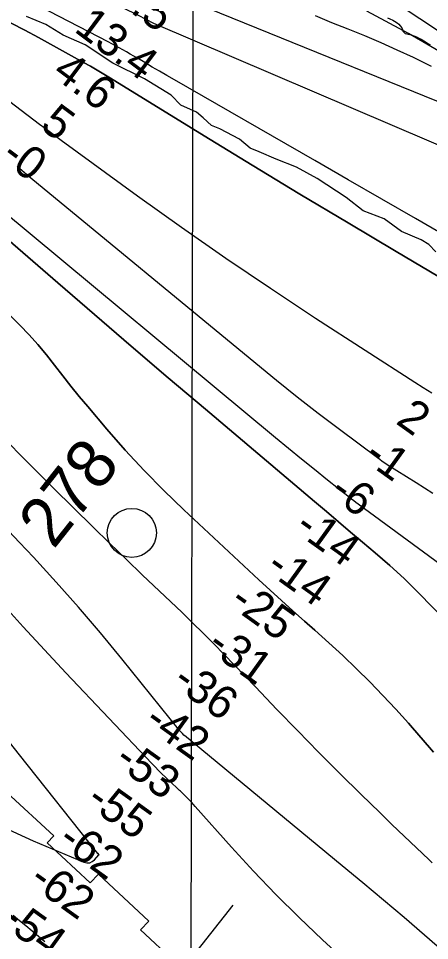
# Model space of a CAD drawing. Extents: x 3187622 to 3225504, y 800805 to 826213.
# Drawn here: x 3201935 to 3202773, y 814771 to 816652 of the extents above; entities that cross this region are included whole.
import ezdxf

# ---------------------------------------------------------------- set-up
doc = ezdxf.new("R2010")
doc.units = 0
for name, color, linetype in [('V-GRID-MAJR', 7, 'Continuous'), ('V-RIVR-EDGE', 7, 'Continuous'), ('V-RIVR-IDEN', 7, 'Continuous'), ('V-RIVR-MILE', 7, 'Continuous'), ('V-RIVR-RANG', 7, 'Continuous'), ('V-ROAD-CNTR', 7, 'Continuous'), ('V-RRAP-RVMT', 7, 'Continuous'), ('V-SITE-VEGE', 7, 'Continuous'), ('V-TOPO-DPTH', 7, 'Continuous'), ('V-TOPO-MAJR', 7, 'Continuous'), ('V-TOPO-MINR', 7, 'Continuous'), ('V-TOPO-WATR', 7, 'Continuous')]:
    doc.layers.add(name, color=color, linetype=linetype)

msp = doc.modelspace()

# ---------------------------------------------------------------- linework, layer by layer
at = {"layer": 'V-GRID-MAJR'}
msp.add_spline([(3202269.1, 806226.1), (3202282.3, 812285.3), (3202295.5, 818347.5), (3202308.8, 824409.7), (3202308.8, 824412.8)], degree=3, dxfattribs=at)
at = {"layer": 'V-RIVR-EDGE'}
msp.add_lwpolyline([(3202785.2, 816176.3), (3202770.9, 816190.7), (3202755.7, 816200.7), (3202715.3, 816217.4), (3202680.2, 816243.5), (3202637.6, 816259.7), (3202602.9, 816286.8), (3202543.5, 816325.6), (3202501.8, 816348.7), (3202460.1, 816364.9), (3202425.4, 816379.8), (3202407.1, 816387.2), (3202385.4, 816405.5), (3202345.5, 816426.9), (3202328.6, 816433.9), (3202311.6, 816449.6), (3202298.2, 816460.9), (3202266.1, 816475.4), (3202246.1, 816495.8), (3202191.9, 816529), (3202127.6, 816560.5), (3202071.2, 816598), (3202026.5, 816618.1), (3201990.9, 816639.5), (3201951.8, 816656.1)], dxfattribs=at)
at = {"layer": 'V-RIVR-MILE'}
msp.add_circle((3202166.4, 815602.7), 50, dxfattribs=at)
at = {"layer": 'V-RIVR-RANG'}
msp.add_line((3201900.2, 814248.2), (3202372.9, 814843.3), dxfattribs=at)
at = {"layer": 'V-ROAD-CNTR'}
msp.add_spline([(3201024.1, 823274.7), (3201018, 823194.2), (3201004.7, 822963.7), (3200987.4, 822858.7), (3200966.9, 822788.4), (3200937.8, 822670.8), (3200879.4, 822446.8), (3200861.2, 822331.3), (3200852.3, 822205.9), (3200846, 822103), (3200850.5, 822002.7), (3200859.8, 821900.4), (3200873.1, 821709.1), (3200906.2, 821470.9), (3200956.6, 821171.3), (3200981.8, 821020.5), (3201004.4, 820882.9), (3201024.9, 820767.6), (3201030.7, 820687.4), (3201025.1, 820574.8), (3201019.7, 820485.6), (3201009.9, 820413.7), (3200981.8, 820299.2), (3200938.6, 820153.1), (3200919.7, 820054.1), (3200905.9, 819899.8), (3200911.1, 819808), (3200923.6, 819715), (3200943.7, 819632.5), (3200990, 819544.5), (3201077.6, 819388.7), (3201164.6, 819241.3), (3201215.4, 819169.2), (3201320.5, 819031.2), (3201438.3, 818874.6), (3201472.9, 818830.2), (3201517.8, 818788.5), (3201613.7, 818704.1), (3201703.7, 818596), (3201763.8, 818510.5), (3201836.1, 818397.9), (3201893.8, 818288.1), (3201910, 818246.3), (3201920.9, 818198.1), (3201929.8, 818155.8), (3201937.9, 818094.1), (3201957.7, 817998.6), (3201977.9, 817926.4), (3202055.4, 817776.5), (3202147, 817624), (3202184.4, 817575.3), (3202228.3, 817509.6), (3202265.9, 817465), (3202335.4, 817389.3), (3202595.4, 817156.1), (3202698.6, 817066.2), (3202845.2, 816933.8), (3202967.2, 816832.3), (3203084.1, 816744.2), (3203205.8, 816662.3), (3203334.5, 816585.9), (3203420.1, 816528.7), (3203529.1, 816448.4), (3203624.3, 816386.4), (3203720.3, 816332.5), (3203800.7, 816304.6), (3203929.1, 816241.3), (3204015.1, 816192.4), (3204112.5, 816105.4), (3204200.5, 816023.3)], degree=3, dxfattribs=at)
at = {"layer": 'V-RRAP-RVMT'}
for p, q in [((3202007.2, 814984.9), (3201912.1, 815073.5)), ((3201994, 814970.7), (3202007.2, 814984.9)), ((3202081.8, 814888.9), (3201994, 814970.7)), ((3202098.4, 814906.7), (3202081.8, 814888.9)), ((3202200.8, 814811.2), (3202098.4, 814906.7)), ((3202184.1, 814793.3), (3202200.8, 814811.2)), ((3202271.8, 814711.4), (3202184.1, 814793.3))]:
    msp.add_line(p, q, dxfattribs=at)
at = {"layer": 'V-SITE-VEGE'}
msp.add_lwpolyline([(3202687.1, 816653.4), (3202691.7, 816650.9), (3202697.9, 816648.5), (3202701.3, 816646.6), (3202706.4, 816643), (3202709.9, 816640.3), (3202712.9, 816637.2), (3202715.8, 816632.7), (3202717.2, 816629.3), (3202718.4, 816625.7), (3202722.9, 816621.5), (3202726.1, 816620.6), (3202735, 816618.5), (3202742.3, 816616.1), (3202747.1, 816613.6), (3202751, 816612), (3202755.8, 816609.5), (3202766.6, 816602.8), (3202770.7, 816600.4), (3202773.5, 816599.1)], dxfattribs=at)
at = {"layer": 'V-TOPO-DPTH'}
for points in [[(3204217.8, 815592.6), (3203668.9, 815938.5), (3203655.2, 815947.1), (3203641.4, 815955.7), (3203627.7, 815964.2), (3203613.9, 815972.7), (3203478, 816056), (3203410.2, 816096.5), (3203341.7, 816135.7), (3203272.2, 816173.1), (3203202, 816209.3), (3203099.7, 816260.5), (3203080, 816269.9), (3203060.2, 816279), (3203040.1, 816287.4), (3203019.7, 816295.4), (3202210.8, 816641.7), (3202179.6, 816657.9), (3202148.3, 816673.9), (3202116.9, 816689.7), (3202024, 816735.9), (3201946.1, 816774.7), (3201868.2, 816813.6)], [(3201920.7, 816642), (3201948.7, 816628), (3201976.3, 816613.2), (3202068.1, 816562.1), (3202082, 816554.3), (3202095.8, 816546.3), (3202109.4, 816538.2), (3202123.1, 816529.9), (3202313.6, 816412.6), (3202411.1, 816353), (3202508.7, 816293.7), (3202606.7, 816234.9), (3202704.9, 816176.4), (3202877.5, 816074.1)], [(3201920.7, 816642), (3201948.7, 816628), (3201976.3, 816613.2), (3202068.1, 816562.1), (3202082, 816554.3), (3202095.8, 816546.3), (3202109.4, 816538.2), (3202123.1, 816529.9), (3202313.6, 816412.6), (3202411.1, 816353), (3202508.7, 816293.7), (3202606.7, 816234.9), (3202704.9, 816176.4), (3202877.5, 816074.1)], [(3202779.4, 815683.2), (3202745, 815704.9), (3202686.6, 815741.9), (3202681.5, 815745.2), (3202676.4, 815748.7), (3202671.4, 815752.2), (3202666.5, 815755.8), (3202589.3, 815813.6), (3202546, 815846.5), (3202503.1, 815879.8), (3202460.6, 815913.7), (3202418.5, 815948.1), (3201960.9, 816326.1), (3201951.5, 816333.9), (3201942.3, 816341.9), (3201933.1, 816350)], [(3202779.4, 815683.2), (3202745, 815704.9), (3202686.6, 815741.9), (3202681.5, 815745.2), (3202676.4, 815748.7), (3202671.4, 815752.2), (3202666.5, 815755.8), (3202589.3, 815813.6), (3202546, 815846.5), (3202503.1, 815879.8), (3202460.6, 815913.7), (3202418.5, 815948.1), (3201960.9, 816326.1), (3201951.5, 816333.9), (3201942.3, 816341.9), (3201933.1, 816350)], [(3201903.4, 816209.7), (3202015.4, 816112.7), (3202090.3, 816048), (3202165.3, 815983.5), (3202240.6, 815919.3), (3202316, 815855.2), (3202538.2, 815666.8), (3202562.7, 815646.1), (3202587.2, 815625.3), (3202611.8, 815604.6), (3202636.3, 815583.9), (3202661.8, 815562.3), (3202691.7, 815536.4), (3202721, 815509.9), (3203068.5, 815159.2), (3203089.5, 815141.7), (3203110.6, 815124.5), (3203131.9, 815107.6), (3203153.4, 815090.8), (3203574.3, 814699.2)], [(3203574.3, 814699.2), (3203153.4, 815090.8), (3203131.9, 815107.6), (3203110.6, 815124.5), (3203089.5, 815141.7), (3203068.5, 815159.2), (3202721, 815509.9), (3202691.7, 815536.4), (3202661.8, 815562.3), (3202636.3, 815583.9), (3202611.8, 815604.6), (3202587.2, 815625.3), (3202562.7, 815646.1), (3202538.2, 815666.8), (3202316, 815855.2), (3202240.6, 815919.3), (3202165.3, 815983.5), (3202090.3, 816048), (3202015.4, 816112.7), (3201903.4, 816209.7)], [(3201836.2, 816126.5), (3201938.1, 816026.2), (3201957, 816006.8), (3201975.2, 815986.9), (3201992.5, 815966.2), (3202009.1, 815945), (3202025.6, 815923.4), (3202042.2, 815902.1), (3202059.2, 815881.1), (3202076.5, 815860.3), (3202115.2, 815814.5), (3202152.7, 815771.6), (3202191.3, 815729.7), (3202231.3, 815689.1), (3202272.3, 815649.5), (3202425, 815507.2), (3202448.1, 815485.9), (3202471.2, 815464.8), (3202494.5, 815443.8), (3202518, 815423), (3202539.1, 815404.3), (3202567.7, 815378.6), (3202595.9, 815352.5), (3202623.5, 815325.8), (3202650.8, 815298.8), (3202677.5, 815271.2), (3202703.8, 815243.2), (3202729.5, 815214.6), (3202754.7, 815185.6), (3202755.3, 815184.9), (3202780.6, 815155.4)], [(3202780.6, 815155.4), (3202755.3, 815184.9), (3202754.7, 815185.6), (3202729.5, 815214.6), (3202703.8, 815243.2), (3202677.5, 815271.2), (3202650.8, 815298.8), (3202623.5, 815325.8), (3202595.9, 815352.5), (3202567.7, 815378.6), (3202539.1, 815404.3), (3202518, 815423), (3202494.5, 815443.8), (3202471.2, 815464.8), (3202448.1, 815485.9), (3202425, 815507.2), (3202272.3, 815649.5), (3202231.3, 815689.1), (3202191.3, 815729.7), (3202152.7, 815771.6), (3202115.2, 815814.5), (3202076.5, 815860.3), (3202059.2, 815881.1), (3202042.2, 815902.1), (3202025.6, 815923.4), (3202009.1, 815945), (3201992.5, 815966.2), (3201975.2, 815986.9), (3201957, 816006.8), (3201938.1, 816026.2), (3201836.2, 816126.5)], [(3201902.1, 815799.5), (3201954.4, 815746.6), (3202007.1, 815694.1), (3202087.5, 815614.8), (3202121, 815582), (3202154.6, 815549.3), (3202188.3, 815516.8), (3202222.3, 815484.4), (3202246, 815461.9), (3202268, 815440.8), (3202289.9, 815419.5), (3202311.6, 815398.1), (3202333.1, 815376.5), (3202354.4, 815354.7), (3202375.7, 815332.9), (3202396.9, 815310.9), (3202418, 815288.9), (3202461.8, 815242.9), (3202504.1, 815199), (3202546.7, 815155.4), (3202589.8, 815112.2), (3202633.2, 815069.3), (3202671.1, 815032.3), (3202695.8, 815008.3), (3202720.7, 814984.3), (3202745.7, 814960.5), (3202770.9, 814936.8), (3202777.9, 814930.2)], [(3202777.9, 814930.2), (3202770.9, 814936.8), (3202745.7, 814960.5), (3202720.7, 814984.3), (3202695.8, 815008.3), (3202671.1, 815032.3), (3202633.2, 815069.3), (3202589.8, 815112.2), (3202546.7, 815155.4), (3202504.1, 815199), (3202461.8, 815242.9), (3202418, 815288.9), (3202396.9, 815310.9), (3202375.7, 815332.9), (3202354.4, 815354.7), (3202333.1, 815376.5), (3202311.6, 815398.1), (3202289.9, 815419.5), (3202268, 815440.8), (3202246, 815461.9), (3202222.3, 815484.4), (3202188.3, 815516.8), (3202154.6, 815549.3), (3202121, 815582), (3202087.5, 815614.8), (3202007.1, 815694.1), (3201954.4, 815746.6), (3201902.1, 815799.5)]]:
    msp.add_lwpolyline(points, dxfattribs=at)
at = {"layer": 'V-TOPO-MAJR'}
for points in [[(3204255.2, 815652.9), (3203706.2, 815992.5), (3203701.3, 815995.5), (3203696.3, 815998.6), (3203691.4, 816001.7), (3203686.5, 816004.8), (3203678.5, 816009.9), (3203677.7, 816010.4), (3203675.9, 816011.6), (3203675, 816012.1), (3203666.3, 816017.8), (3203661.1, 816021.2), (3203655.8, 816024.6), (3203650.6, 816028), (3203645.4, 816031.5), (3203179.2, 816341.1), (3203154, 816357.7), (3203128.8, 816374.2), (3203103.5, 816390.5), (3203078, 816406.8), (3202894.2, 816523.3), (3202812.3, 816573.3), (3202729.4, 816621.4), (3202645, 816666.8)], [(3202803.7, 814746.6), (3202762.1, 814782.5), (3202720.6, 814818.1), (3202678.9, 814853.6), (3202637, 814888.8), (3202594.9, 814923.8), (3202273.5, 815189.5), (3202273.1, 815189.9), (3202272.2, 815190.6), (3202269.2, 815193.5), (3202266, 815197), (3202264.8, 815198.5), (3202264.2, 815199.2), (3202146.1, 815346.1), (3202102.5, 815399.1), (3202058, 815451.4), (3202012.4, 815502.6), (3201966, 815553.1), (3201937.8, 815583.1), (3201904.7, 815618)]]:
    msp.add_lwpolyline(points, dxfattribs=at)
at = {"layer": 'V-TOPO-MINR'}
for points in [[(3204027.1, 815824.8), (3203733.7, 816024.2), (3203716.7, 816035.6), (3203699.6, 816046.7), (3203682.3, 816057.6), (3203665, 816068.4), (3203441.7, 816204), (3203391.4, 816234.9), (3203341.2, 816266), (3203291.3, 816297.4), (3203241.6, 816329.1), (3203156.6, 816383.7), (3203149.4, 816388.3), (3203142.3, 816393), (3203135.2, 816397.6), (3203128.1, 816402.3), (3202564.1, 816776.6), (3202531, 816798.2), (3202497.7, 816819.6), (3202464.1, 816840.5), (3202430.4, 816861.1), (3202427.8, 816862.7), (3201556.2, 817191.3)], [(3204217.8, 815592.6), (3203668.9, 815938.5), (3203655.2, 815947.1), (3203641.4, 815955.7), (3203627.7, 815964.2), (3203613.9, 815972.7), (3203478, 816056), (3203410.2, 816096.5), (3203341.7, 816135.7), (3203272.2, 816173.1), (3203202, 816209.3), (3203099.7, 816260.5), (3203080, 816269.9), (3203060.2, 816279), (3203040.1, 816287.4), (3203019.7, 816295.4), (3202210.8, 816641.7), (3202179.6, 816657.9), (3202148.3, 816673.9), (3202116.9, 816689.7), (3202024, 816735.9), (3201946.1, 816774.7), (3201868.2, 816813.6)], [(3202812.1, 816204.4), (3202743.8, 816244), (3202675.5, 816283.5), (3202607.1, 816323), (3202538.7, 816362.4), (3202253, 816526.7), (3202237.9, 816535.4), (3202222.9, 816544.1), (3202207.9, 816552.9), (3202192.9, 816561.8), (3202177.6, 816570.8), (3202170.2, 816575.1), (3202162.9, 816579.4), (3202155.5, 816583.7), (3202148.1, 816587.9), (3202140.6, 816592.1), (3202133.2, 816596.2), (3202125.6, 816600.2), (3202118.1, 816604.2), (3201878.6, 816728.5)], [(3202959.8, 816413.4), (3202273.9, 816692.9)], [(3202776.5, 816554.1), (3202739.6, 816572.1), (3202706.9, 816587.5), (3202674, 816602.4), (3202640.6, 816616.4), (3202607.1, 816629.9), (3202573.5, 816643.3), (3202540.1, 816657.2)], [(3202776.9, 815887.6), (3202759.6, 815898.5), (3202742.3, 815909.6), (3202540.4, 816040.3), (3202448.6, 816100.9), (3202357.5, 816162.4), (3202267.4, 816225.5), (3202178.1, 816289.6), (3202022.4, 816403.3), (3202011.4, 816411.3), (3202000.5, 816419.4), (3201989.5, 816427.6), (3201978.6, 816435.8), (3201880.1, 816510.6)], [(3202779.4, 815683.2), (3202745, 815704.9), (3202686.6, 815741.9), (3202681.5, 815745.2), (3202676.4, 815748.7), (3202671.4, 815752.2), (3202666.5, 815755.8), (3202589.3, 815813.6), (3202546, 815846.5), (3202503.1, 815879.8), (3202460.6, 815913.7), (3202418.5, 815948.1), (3201960.9, 816326.1), (3201951.5, 816333.9), (3201942.3, 816341.9), (3201933.1, 816350)], [(3203115.7, 815301.5), (3202627.3, 815661.5), (3202622.8, 815664.9), (3202618.3, 815668.3), (3202613.9, 815671.7), (3202609.4, 815675.2), (3202564.8, 815710.6), (3202538.1, 815731.8), (3202511.5, 815753.2), (3202485.1, 815774.8), (3202458.8, 815796.5), (3201898.6, 816262.7)], [(3203574.3, 814699.2), (3203153.4, 815090.8), (3203131.9, 815107.6), (3203110.6, 815124.5), (3203089.5, 815141.7), (3203068.5, 815159.2), (3202721, 815509.9), (3202691.7, 815536.4), (3202661.8, 815562.3), (3202636.3, 815583.9), (3202611.8, 815604.6), (3202587.2, 815625.3), (3202562.7, 815646.1), (3202538.2, 815666.8), (3202316, 815855.2), (3202240.6, 815919.3), (3202165.3, 815983.5), (3202090.3, 816048), (3202015.4, 816112.7), (3201903.4, 816209.7)], [(3202780.6, 815155.4), (3202755.3, 815184.9), (3202754.7, 815185.6), (3202729.5, 815214.6), (3202703.8, 815243.2), (3202677.5, 815271.2), (3202650.8, 815298.8), (3202623.5, 815325.8), (3202595.9, 815352.5), (3202567.7, 815378.6), (3202539.1, 815404.3), (3202518, 815423), (3202494.5, 815443.8), (3202471.2, 815464.8), (3202448.1, 815485.9), (3202425, 815507.2), (3202272.3, 815649.5), (3202231.3, 815689.1), (3202191.3, 815729.7), (3202152.7, 815771.6), (3202115.2, 815814.5), (3202076.5, 815860.3), (3202059.2, 815881.1), (3202042.2, 815902.1), (3202025.6, 815923.4), (3202009.1, 815945), (3201992.5, 815966.2), (3201975.2, 815986.9), (3201957, 816006.8), (3201938.1, 816026.2), (3201836.2, 816126.5)], [(3202777.9, 814930.2), (3202770.9, 814936.8), (3202745.7, 814960.5), (3202720.7, 814984.3), (3202695.8, 815008.3), (3202671.1, 815032.3), (3202633.2, 815069.3), (3202589.8, 815112.2), (3202546.7, 815155.4), (3202504.1, 815199), (3202461.8, 815242.9), (3202418, 815288.9), (3202396.9, 815310.9), (3202375.7, 815332.9), (3202354.4, 815354.7), (3202333.1, 815376.5), (3202311.6, 815398.1), (3202289.9, 815419.5), (3202268, 815440.8), (3202246, 815461.9), (3202222.3, 815484.4), (3202188.3, 815516.8), (3202154.6, 815549.3), (3202121, 815582), (3202087.5, 815614.8), (3202007.1, 815694.1), (3201954.4, 815746.6), (3201902.1, 815799.5)], [(3202762.1, 814581.6), (3202554.9, 814772.8), (3202506.8, 814818.5), (3202459.7, 814865.1), (3202414, 814913), (3202369.2, 814961.9), (3202295.6, 815044.6), (3202288.2, 815052.7), (3202280.7, 815060.7), (3202272.9, 815068.4), (3202265.1, 815076.1), (3202263.4, 815077.6), (3202256.3, 815084.4), (3202249.1, 815091.1), (3202242, 815097.9), (3202234.8, 815104.7), (3202227.7, 815111.5), (3202220.7, 815118.4), (3202213.8, 815125.4), (3202207, 815132.5), (3202032, 815317.4), (3201988.3, 815364.1), (3201945, 815411.1), (3201902.3, 815458.7)], [(3201907.8, 815001.4), (3201965.1, 814975.1), (3202068.8, 814931.2), (3202074.8, 814930), (3202080.5, 814930.2), (3202085.7, 814932.4), (3202090.6, 814936.1), (3202099.3, 814945.9), (3202099.4, 814946.2), (3202099.5, 814946.4), (3202099.4, 814946.7), (3202097.5, 814948.7), (3202097.3, 814949), (3201937.6, 815150.5), (3201917.4, 815176.2)], [(3201924.5, 814823.1), (3201937.5, 814812.5), (3201950.5, 814801.9), (3201963.4, 814791.2), (3201976.3, 814780.4), (3201989.1, 814769.6)]]:
    msp.add_lwpolyline(points, dxfattribs=at)
at = {"layer": 'V-TOPO-WATR'}
msp.add_lwpolyline([(3202877.5, 816074.1), (3202704.9, 816176.4), (3202606.7, 816234.9), (3202508.7, 816293.7), (3202411.1, 816353), (3202313.6, 816412.6), (3202123.1, 816529.9), (3202109.4, 816538.2), (3202095.8, 816546.3), (3202082, 816554.3), (3202068.1, 816562.1), (3201976.3, 816613.2), (3201948.7, 816628), (3201920.7, 816642)], dxfattribs=at)

# ---------------------------------------------------------------- texts
at = {"layer": 'V-RIVR-IDEN'}
msp.add_text('278', height=100, rotation=51.7456, dxfattribs=at).set_placement((3202006.9, 815567.6))
at = {"layer": 'V-RIVR-RANG'}
for s, rotation, p in [('19.5', 322.9683, (3202081.9, 816725.8)), ('13.4', 323.243, (3202046.6, 816626.7)), ('4.6', 323.243, (3202001.6, 816535.5)), ('5', 323.243, (3201977.1, 816429)), ('-0', 323.243, (3201896.5, 816364.3)), ('2', 324.2687, (3202701.7, 815827.2)), ('-1', 324.2687, (3202635.2, 815751.8)), ('-6', 324.2687, (3202565.3, 815679)), ('-14', 324.2687, (3202494.5, 815606.7)), ('-14', 324.2687, (3202435.9, 815525.7)), ('-25', 324.2687, (3202362.1, 815455.6)), ('-31', 324.2687, (3202315.7, 815365.8)), ('-36', 324.2687, (3202245.7, 815292.9)), ('-42', 324.2687, (3202188, 815211.3)), ('-53', 324.2687, (3202127.3, 815131.8)), ('-55', 324.2687, (3202069.9, 815049.8)), ('-62', 324.2687, (3202012.2, 814968.2)), ('-62', 324.2687, (3201953.6, 814887.1)), ('-54', 324.2687, (3201895.7, 814805.6))]:
    msp.add_text(s, height=67, rotation=rotation, dxfattribs=at).set_placement(p)

doc.saveas('drawing.dxf')
